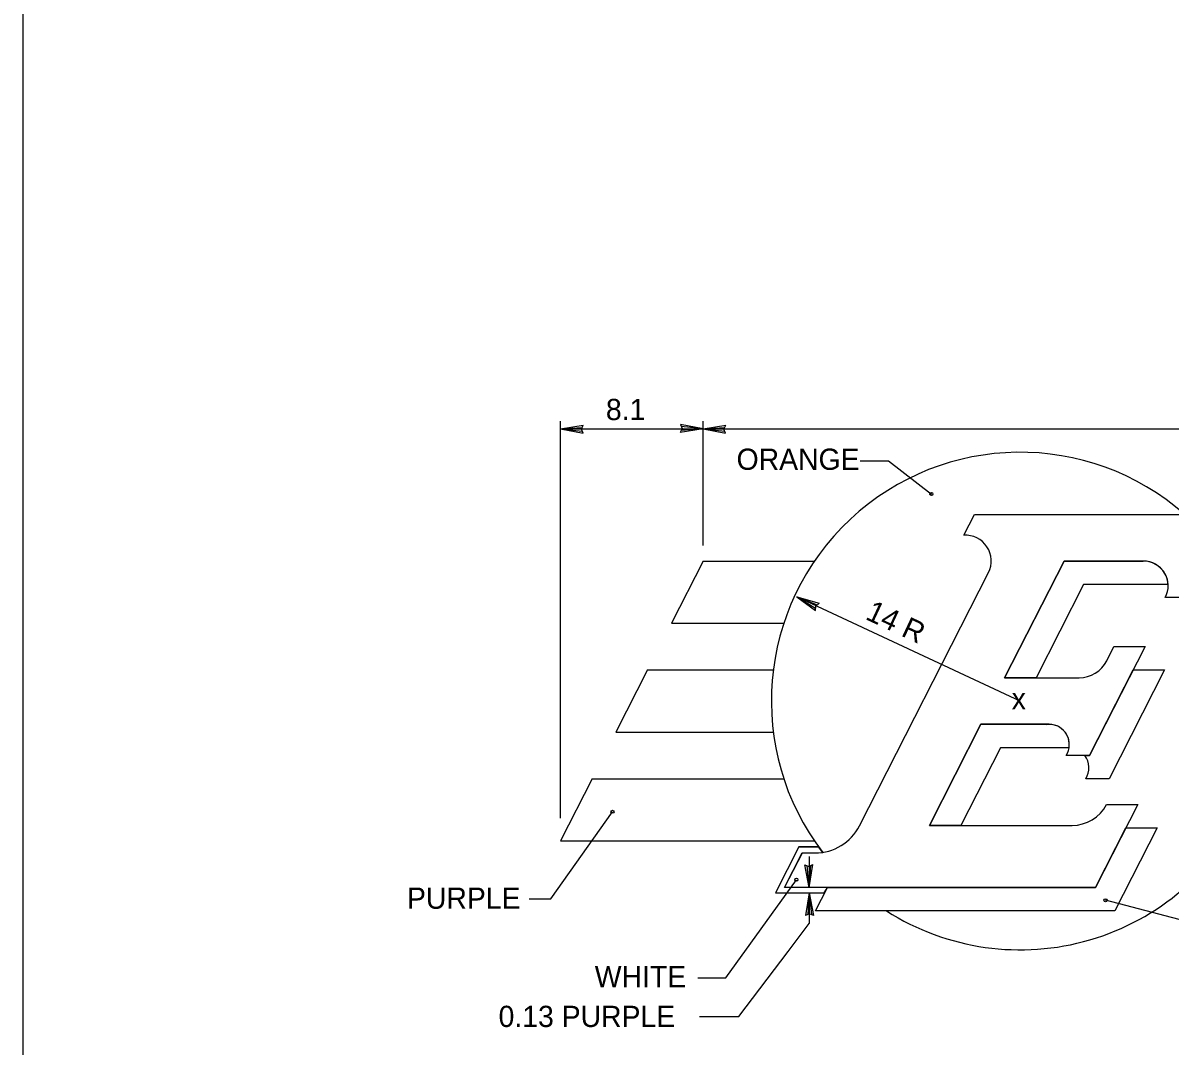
# Model space of a CAD drawing. Extents: x 10268197 to 10268826, y 2141503 to 2142677.
# Drawn here: x 10268664.32 to 10268696.97, y 2142372.34 to 2142401.45 of the extents above; entities that cross this region are included whole.
import ezdxf

# ---------------------------------------------------------------- set-up
doc = ezdxf.new("R2010")
doc.units = 0
for name, color, linetype in [('1', 7, 'Continuous'), ('Default', 7, 'Continuous'), ('NonPlottingEle_dp', 7, 'Continuous')]:
    doc.layers.add(name, color=color, linetype=linetype)

msp = doc.modelspace()

# ---------------------------------------------------------------- linework, layer by layer
at = {"layer": '1'}
for p, q in [((10268679.621, 2142378.822), (10268679.621, 2142390.119)), ((10268683.675, 2142386.58), (10268683.675, 2142390.119)), ((10268679.621, 2142389.898), (10268702.823, 2142389.898)), ((10268688.152, 2142388.987), (10268688.953, 2142388.987)), ((10268688.953, 2142388.987), (10268690.173, 2142388.045)), ((10268692.7, 2142382.155), (10268686.347, 2142385.118)), ((10268679.343, 2142376.527), (10268681.101, 2142379.005)), ((10268686.699, 2142377.733), (10268686.699, 2142376.853)), ((10268684.325, 2142374.282), (10268686.332, 2142377.071)), ((10268686.699, 2142376.696), (10268686.699, 2142375.823)), ((10268678.729, 2142376.527), (10268679.343, 2142376.527)), ((10268697.402, 2142375.891), (10268695.13, 2142376.486)), ((10268686.099, 2142375.031), (10268686.699, 2142375.823)), ((10268684.695, 2142373.178), (10268686.099, 2142375.031)), ((10268683.524, 2142374.282), (10268684.325, 2142374.282)), ((10268683.571, 2142373.178), (10268684.695, 2142373.178))]:
    msp.add_line(p, q, dxfattribs=at)
for centre in [(10268690.173, 2142388.044), (10268681.101, 2142379.004), (10268686.332, 2142377.071), (10268695.13, 2142376.485)]:
    msp.add_circle(centre, 0.0442, dxfattribs=at)
at = {"layer": 'Default'}
for p, q in [((10268679.621, 2142389.898), (10268680.268, 2142390.001)), ((10268679.621, 2142389.898), (10268680.24, 2142389.941)), ((10268679.621, 2142389.898), (10268680.264, 2142389.773)), ((10268679.621, 2142389.898), (10268680.239, 2142389.833)), ((10268680.216, 2142389.888), (10268680.268, 2142390.001)), ((10268680.264, 2142389.773), (10268680.216, 2142389.888)), ((10268683.079, 2142389.908), (10268683.028, 2142389.795)), ((10268683.675, 2142389.898), (10268683.028, 2142389.795)), ((10268683.675, 2142389.898), (10268683.031, 2142390.023)), ((10268683.031, 2142390.023), (10268683.079, 2142389.908)), ((10268683.675, 2142389.898), (10268683.055, 2142389.855)), ((10268683.675, 2142389.898), (10268683.056, 2142389.963)), ((10268683.675, 2142389.898), (10268684.321, 2142390.001)), ((10268683.675, 2142389.898), (10268684.294, 2142389.941)), ((10268683.675, 2142389.898), (10268684.317, 2142389.773)), ((10268683.675, 2142389.898), (10268684.292, 2142389.833)), ((10268684.27, 2142389.888), (10268684.321, 2142390.001)), ((10268684.317, 2142389.773), (10268684.27, 2142389.888)), ((10268691.099, 2142386.871), (10268691.401, 2142387.465)), ((10268691.401, 2142387.465), (10268698.922, 2142387.465)), ((10268683.675, 2142386.137), (10268682.774, 2142384.368)), ((10268683.675, 2142386.137), (10268686.847, 2142386.137)), ((10268693.95, 2142386.137), (10268692.259, 2142382.819)), ((10268692.259, 2142382.819), (10268693.95, 2142386.137)), ((10268692.259, 2142382.819), (10268693.95, 2142386.137)), ((10268696.205, 2142386.137), (10268693.95, 2142386.137)), ((10268693.95, 2142386.137), (10268696.205, 2142386.137)), ((10268693.95, 2142386.137), (10268696.205, 2142386.137)), ((10268688.126, 2142378.605), (10268691.798, 2142385.812)), ((10268694.506, 2142385.474), (10268693.153, 2142382.819)), ((10268694.506, 2142385.474), (10268693.153, 2142382.819)), ((10268696.912, 2142385.474), (10268694.506, 2142385.474)), ((10268696.912, 2142385.474), (10268694.506, 2142385.474)), ((10268686.347, 2142385.118), (10268686.977, 2142384.937)), ((10268686.347, 2142385.118), (10268686.877, 2142384.733)), ((10268686.347, 2142385.118), (10268686.88, 2142384.798)), ((10268686.347, 2142385.118), (10268686.927, 2142384.895)), ((10268686.877, 2142384.733), (10268686.882, 2142384.857)), ((10268686.882, 2142384.857), (10268686.977, 2142384.937)), ((10268697.717, 2142385.099), (10268696.832, 2142385.099)), ((10268682.774, 2142384.368), (10268685.976, 2142384.368)), ((10268696.254, 2142383.704), (10268694.676, 2142380.607)), ((10268695.164, 2142383.302), (10268695.369, 2142383.704)), ((10268695.369, 2142383.704), (10268696.254, 2142383.704)), ((10268682.098, 2142383.04), (10268681.198, 2142381.271)), ((10268682.098, 2142383.04), (10268685.676, 2142383.04)), ((10268694.676, 2142380.607), (10268695.916, 2142383.04)), ((10268694.676, 2142380.607), (10268695.916, 2142383.04)), ((10268696.81, 2142383.04), (10268695.232, 2142379.943)), ((10268696.81, 2142383.04), (10268695.232, 2142379.943)), ((10268695.916, 2142383.04), (10268696.81, 2142383.04)), ((10268695.916, 2142383.04), (10268696.81, 2142383.04)), ((10268692.259, 2142382.819), (10268694.376, 2142382.819)), ((10268693.153, 2142382.819), (10268692.259, 2142382.819)), ((10268693.153, 2142382.819), (10268692.259, 2142382.819)), ((10268681.198, 2142381.271), (10268685.676, 2142381.271)), ((10268691.583, 2142381.492), (10268690.118, 2142378.616)), ((10268690.118, 2142378.616), (10268691.583, 2142381.492)), ((10268690.118, 2142378.616), (10268691.583, 2142381.492)), ((10268693.525, 2142381.492), (10268691.583, 2142381.492)), ((10268691.583, 2142381.492), (10268693.442, 2142381.486)), ((10268691.583, 2142381.492), (10268693.442, 2142381.486)), ((10268692.138, 2142380.827), (10268691.012, 2142378.616)), ((10268692.138, 2142380.827), (10268691.012, 2142378.616)), ((10268694.092, 2142380.82), (10268692.138, 2142380.827)), ((10268694.092, 2142380.82), (10268692.138, 2142380.827)), ((10268694.676, 2142380.607), (10268694.01, 2142380.607)), ((10268694.537, 2142380.607), (10268694.676, 2142380.607)), ((10268694.537, 2142380.607), (10268694.676, 2142380.607)), ((10268680.522, 2142379.943), (10268679.621, 2142378.174)), ((10268680.522, 2142379.943), (10268685.976, 2142379.943)), ((10268695.232, 2142379.943), (10268694.568, 2142379.943)), ((10268695.232, 2142379.943), (10268694.568, 2142379.943)), ((10268696.045, 2142379.212), (10268694.84, 2142376.846)), ((10268695.16, 2142379.212), (10268696.045, 2142379.212)), ((10268690.118, 2142378.616), (10268694.179, 2142378.616)), ((10268691.012, 2142378.616), (10268690.118, 2142378.616)), ((10268691.012, 2142378.616), (10268690.118, 2142378.616)), ((10268694.84, 2142376.846), (10268695.707, 2142378.548)), ((10268694.84, 2142376.846), (10268695.707, 2142378.548)), ((10268696.601, 2142378.548), (10268695.395, 2142376.183)), ((10268696.601, 2142378.548), (10268695.395, 2142376.183)), ((10268695.707, 2142378.548), (10268696.601, 2142378.548)), ((10268695.707, 2142378.548), (10268696.601, 2142378.548)), ((10268679.621, 2142378.174), (10268686.847, 2142378.174)), ((10268686.401, 2142378.005), (10268685.735, 2142376.696)), ((10268686.401, 2142378.005), (10268686.965, 2142378.005)), ((10268685.991, 2142376.846), (10268686.493, 2142377.832)), ((10268686.493, 2142377.832), (10268686.865, 2142377.832)), ((10268686.699, 2142376.853), (10268686.574, 2142377.496)), ((10268686.574, 2142377.496), (10268686.689, 2142377.449)), ((10268686.699, 2142376.853), (10268686.635, 2142377.471)), ((10268686.689, 2142377.449), (10268686.802, 2142377.5)), ((10268686.699, 2142376.853), (10268686.802, 2142377.5)), ((10268686.699, 2142376.853), (10268686.742, 2142377.472)), ((10268685.735, 2142376.696), (10268687.123, 2142376.696)), ((10268694.84, 2142376.846), (10268685.991, 2142376.846)), ((10268686.699, 2142376.696), (10268686.596, 2142376.049)), ((10268686.699, 2142376.696), (10268686.656, 2142376.077)), ((10268686.699, 2142376.696), (10268686.824, 2142376.053)), ((10268686.699, 2142376.696), (10268686.764, 2142376.077)), ((10268686.876, 2142376.183), (10268687.214, 2142376.846)), ((10268686.876, 2142376.183), (10268687.214, 2142376.846)), ((10268687.214, 2142376.846), (10268694.84, 2142376.846)), ((10268687.214, 2142376.846), (10268694.84, 2142376.846)), ((10268686.709, 2142376.1), (10268686.596, 2142376.049)), ((10268686.824, 2142376.053), (10268686.709, 2142376.1)), ((10268695.395, 2142376.183), (10268686.876, 2142376.183)), ((10268695.395, 2142376.183), (10268686.876, 2142376.183))]:
    msp.add_line(p, q, dxfattribs=at)
msp.add_lwpolyline([(10268686.965, 2142378.005), (10268686.401, 2142378.005), (10268685.735, 2142376.696), (10268687.123, 2142376.696), (10268687.214, 2142376.846), (10268685.991, 2142376.846), (10268686.507, 2142377.831), (10268686.87, 2142377.831), (10268687.082, 2142377.848)], close=True, dxfattribs=at)
for centre, radius, start, end in [((10268692.7, 2142382.155), 7.079, 48.5904, 217.4727), ((10268691.147, 2142386.142), 0.73, 332.9998, 93.8045), ((10268696.205, 2142385.429), 0.708, 332.2089, 90), ((10268696.205, 2142385.429), 0.708, 3.5833, 90), ((10268696.205, 2142385.429), 0.708, 3.5833, 90), ((10268694.376, 2142383.703), 0.885, 270, 332.9883), ((10268693.525, 2142380.916), 0.575, 350.3502, 98.3344), ((10268693.525, 2142380.916), 0.575, 350.3502, 98.3344), ((10268693.525, 2142380.916), 0.575, 327.421, 90), ((10268694.084, 2142380.252), 0.575, 327.421, 37.9799), ((10268694.084, 2142380.252), 0.575, 327.421, 37.9799), ((10268692.7, 2142382.155), 7.079, 237.5383, 335.047), ((10268694.178, 2142379.721), 1.106, 270, 332.5096), ((10268686.865, 2142379.247), 1.416, 270, 332.9991)]:
    msp.add_arc(centre, radius, start, end, dxfattribs=at)
at = {"layer": 'NonPlottingEle_dp'}
msp.add_line((10268664.322, 2142431.588), (10268664.322, 2142335.588), dxfattribs=at)

# ---------------------------------------------------------------- texts
at = {"layer": '1'}
for s, height, p in [('8.1', 0.6037, (10268680.912, 2142390.149)), ('ORANGE', 0.6037, (10268684.631, 2142388.733)), ('x', 0.604, (10268692.46, 2142381.919)), ('PURPLE', 0.6037, (10268675.251, 2142376.244)), ('WHITE', 0.6037, (10268680.595, 2142374.011)), ('0.13 PURPLE', 0.60368, (10268677.858, 2142372.88))]:
    msp.add_text(s, height=height, dxfattribs=at).set_placement(p)
msp.add_text('14 R', height=0.6037, rotation=334.9991, dxfattribs=at).set_placement((10268688.268, 2142384.496))

doc.saveas('drawing.dxf')
